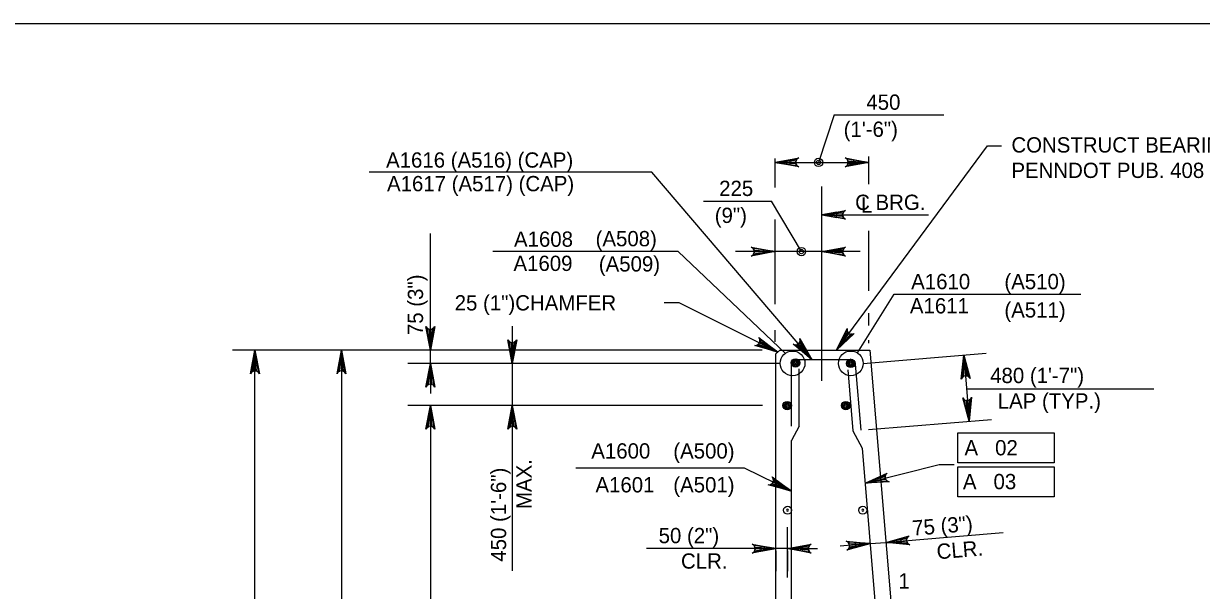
# Model space of a CAD drawing. Extents: x 634540 to 640306, y 296059 to 300275.
# Drawn here: x 638955.4 to 639186.9, y 297715.1 to 297826.5 of the extents above; entities that cross this region are included whole.
import ezdxf

# ---------------------------------------------------------------- set-up
doc = ezdxf.new("R2010")
doc.units = 0
for name, color, linetype in [('2', 7, 'Continuous'), ('3', 7, 'Continuous'), ('4', 7, 'Continuous'), ('5', 7, 'Continuous'), ('9', 7, 'Continuous')]:
    doc.layers.add(name, color=color, linetype=linetype)

# ---------------------------------------------------------------- blocks, each defined once
blk = doc.blocks.new('B')
at = {"layer": '3'}
blk.add_circle((0, 0), 0.16, dxfattribs=at)
for start, end in [(0, 180), (180, 0)]:
    blk.add_arc((0, 0), 0.0391, start, end, dxfattribs=at)

msp = doc.modelspace()

# ---------------------------------------------------------------- linework, layer by layer
at = {"layer": '2'}
msp.add_line((638475.46, 297826.46), (639261.46, 297826.46), dxfattribs=at)
at = {"layer": '3'}
for p, q in [((639114.72, 297808.54), (639111.68, 297799.18)), ((639114.72, 297808.54), (639136.3, 297808.54)), ((639115.23, 297762.31), (639144.88, 297802.43)), ((639144.88, 297802.43), (639147.63, 297802.43)), ((639103.11, 297794.22), (639103.11, 297799.92)), ((639103.11, 297799.18), (639121.57, 297799.18)), ((639121.57, 297794.93), (639121.57, 297800.35)), ((639121.57, 297799.18), (639121.57, 297799.18)), ((639078.88, 297797.23), (639023.32, 297797.23)), ((639110.37, 297760.48), (639078.88, 297797.23)), ((639112.33, 297756.26), (639112.33, 297794.45)), ((639089.02, 297791.54), (639102.44, 297791.54)), ((639108.3, 297781.65), (639102.45, 297791.54)), ((639103.11, 297771.35), (639103.11, 297787.98)), ((639112.33, 297788.88), (639133.31, 297788.88)), ((639035.36, 297759.69), (639035.36, 297785.19)), ((639103.11, 297781.66), (639103.11, 297786.36)), ((639103.11, 297783.06), (639103.11, 297786.08)), ((639121.57, 297773.97), (639121.57, 297785.71)), ((639119.87, 297781.65), (639095.37, 297781.65)), ((639084.26, 297771.61), (639081.31, 297771.61)), ((639103.68, 297761.92), (639084.26, 297771.61)), ((639121.57, 297767.16), (639121.57, 297769.58)), ((639035.36, 297762.31), (639035.36, 297768.21)), ((639051.45, 297767), (639051.45, 297718.96)), ((639103.11, 297763.93), (639103.11, 297766.24)), ((639121.57, 297763.69), (639121.57, 297764.27)), ((639030.22, 297762.31), (638996.44, 297762.31)), ((639000.87, 297600.58), (639000.87, 297762.31)), ((639100.59, 297762.31), (639013.44, 297762.31)), ((639017.87, 297762.31), (639017.87, 297693.66)), ((639017.87, 297762.31), (639017.87, 297762.31)), ((639065.46, 297762.31), (639030.93, 297762.31)), ((639104.04, 297759.69), (639030.93, 297759.69)), ((639035.36, 297759.69), (639035.36, 297753.78)), ((639120.42, 297759.67), (639144.62, 297761.69)), ((639140.2, 297761.32), (639141.29, 297748.32)), ((639140.76, 297754.66), (639177.61, 297754.66)), ((639100.62, 297751.4), (639030.93, 297751.4)), ((639035.36, 297751.4), (639035.36, 297627.86)), ((639121.51, 297746.67), (639145.7, 297748.69)), ((639139.06, 297740.13), (639139.06, 297746.04)), ((639139.06, 297746.04), (639158.01, 297746.04)), ((639158.01, 297746.04), (639158.01, 297740.13)), ((639097.14, 297739.09), (639063.97, 297739.09)), ((639106.36, 297734.57), (639097.14, 297739.09)), ((639120.84, 297736.14), (639135.37, 297739.85)), ((639135.37, 297739.85), (639138.32, 297739.85)), ((639158.01, 297740.13), (639139.06, 297740.13)), ((639139.06, 297739.39), (639158.01, 297739.39)), ((639139.06, 297733.48), (639139.06, 297739.39)), ((639158.01, 297739.39), (639158.01, 297733.48)), ((639158.01, 297733.48), (639139.06, 297733.48)), ((639103.29, 297724.55), (639103.29, 297727.49)), ((639105.58, 297717.61), (639105.58, 297727.49)), ((639124.89, 297724.53), (639130.78, 297725.02)), ((639130.78, 297725.02), (639147.97, 297726.45)), ((639097.38, 297723.3), (639077.86, 297723.3)), ((639100.34, 297723.3), (639097.38, 297723.3)), ((639105.58, 297723.3), (639103.29, 297723.3)), ((639103.29, 297722.86), (639103.29, 297718.87)), ((639105.58, 297722.86), (639105.58, 297718.87)), ((639108.53, 297723.3), (639111.48, 297723.3)), ((639121.83, 297724.28), (639115.94, 297723.79)), ((639121.83, 297724.28), (639124.89, 297724.53))]:
    msp.add_line(p, q, dxfattribs=at)
for points in [[(639103.11, 297799.18), (639107.77, 297800.05), (639107.41, 297799.81), (639107.22, 297799.49), (639107.17, 297799.18), (639107.22, 297798.87), (639107.41, 297798.56), (639107.77, 297798.31), (639103.11, 297799.18), (639107.41, 297798.56), (639107.22, 297798.87), (639103.11, 297799.18), (639107.17, 297799.18), (639107.22, 297799.49), (639103.11, 297799.18), (639107.41, 297799.81)], [(639121.57, 297799.18), (639116.91, 297798.31), (639117.27, 297798.56), (639117.45, 297798.87), (639117.51, 297799.18), (639117.45, 297799.49), (639117.27, 297799.81), (639116.91, 297800.05), (639121.57, 297799.18), (639117.27, 297799.81), (639117.45, 297799.49), (639121.57, 297799.18), (639117.51, 297799.18), (639117.45, 297798.87), (639121.57, 297799.18), (639117.27, 297798.56)], [(639112.33, 297788.88), (639117, 297789.75), (639116.64, 297789.5), (639116.45, 297789.19), (639116.4, 297788.88), (639116.45, 297788.57), (639116.64, 297788.25), (639117, 297788.01), (639112.33, 297788.88), (639116.64, 297788.25), (639116.45, 297788.57), (639112.33, 297788.88), (639116.4, 297788.88), (639116.45, 297789.19), (639112.33, 297788.88), (639116.64, 297789.5)], [(639103.11, 297781.65), (639098.44, 297780.78), (639098.8, 297781.02), (639098.99, 297781.34), (639099.04, 297781.65), (639098.99, 297781.96), (639098.8, 297782.27), (639098.44, 297782.52), (639103.11, 297781.65), (639098.8, 297782.27), (639098.99, 297781.96), (639103.11, 297781.65), (639099.04, 297781.65), (639098.99, 297781.34), (639103.11, 297781.65), (639098.8, 297781.02)], [(639112.33, 297781.65), (639117, 297782.52), (639116.64, 297782.27), (639116.45, 297781.96), (639116.4, 297781.65), (639116.45, 297781.34), (639116.64, 297781.02), (639117, 297780.78), (639112.33, 297781.65), (639116.64, 297781.02), (639116.45, 297781.34), (639112.33, 297781.65), (639116.4, 297781.65), (639116.45, 297781.96), (639112.33, 297781.65), (639116.64, 297782.27)], [(639035.36, 297762.31), (639034.49, 297766.97), (639034.74, 297766.61), (639035.05, 297766.42), (639035.36, 297766.37), (639035.67, 297766.42), (639035.99, 297766.61), (639036.23, 297766.97), (639035.36, 297762.31), (639035.99, 297766.61), (639035.67, 297766.42), (639035.36, 297762.31), (639035.36, 297766.37), (639035.05, 297766.42), (639035.36, 297762.31), (639034.74, 297766.61)], [(639115.23, 297762.31), (639117.3, 297766.57), (639117.29, 297766.14), (639117.43, 297765.8), (639117.65, 297765.57), (639117.93, 297765.43), (639118.29, 297765.4), (639118.7, 297765.54), (639115.23, 297762.31), (639118.29, 297765.4), (639117.93, 297765.43), (639115.23, 297762.31), (639117.65, 297765.57), (639117.43, 297765.8), (639115.23, 297762.31), (639117.29, 297766.14)], [(639051.45, 297759.69), (639050.58, 297764.35), (639050.83, 297763.99), (639051.14, 297763.81), (639051.45, 297763.75), (639051.77, 297763.81), (639052.08, 297763.99), (639052.33, 297764.35), (639051.45, 297759.69), (639052.08, 297763.99), (639051.77, 297763.81), (639051.45, 297759.69), (639051.45, 297763.75), (639051.14, 297763.81), (639051.45, 297759.69), (639050.83, 297763.99)], [(639103.68, 297761.92), (639099.12, 297763.22), (639099.55, 297763.29), (639099.85, 297763.48), (639100.04, 297763.74), (639100.13, 297764.04), (639100.11, 297764.41), (639099.9, 297764.79), (639103.68, 297761.92), (639100.11, 297764.41), (639100.13, 297764.04), (639103.68, 297761.92), (639100.04, 297763.74), (639099.85, 297763.48), (639103.68, 297761.92), (639099.55, 297763.29)], [(639110.37, 297760.48), (639106.67, 297763.45), (639107.09, 297763.34), (639107.45, 297763.4), (639107.72, 297763.57), (639107.92, 297763.81), (639108.04, 297764.15), (639108, 297764.59), (639110.37, 297760.48), (639108.04, 297764.15), (639107.92, 297763.81), (639110.37, 297760.48), (639107.72, 297763.57), (639107.45, 297763.4), (639110.37, 297760.48), (639107.09, 297763.34)], [(639000.87, 297762.31), (639001.74, 297757.65), (639001.49, 297758), (639001.18, 297758.19), (639000.87, 297758.24), (639000.56, 297758.19), (639000.24, 297758), (639000, 297757.65), (639000.87, 297762.31), (639000.24, 297758), (639000.56, 297758.19), (639000.87, 297762.31), (639000.87, 297758.24), (639001.18, 297758.19), (639000.87, 297762.31), (639001.49, 297758)], [(639017.87, 297762.31), (639018.75, 297757.65), (639018.5, 297758), (639018.19, 297758.19), (639017.87, 297758.24), (639017.56, 297758.19), (639017.25, 297758), (639017, 297757.65), (639017.87, 297762.31), (639017.25, 297758), (639017.56, 297758.19), (639017.87, 297762.31), (639017.87, 297758.24), (639018.19, 297758.19), (639017.87, 297762.31), (639018.5, 297758)], [(639035.36, 297759.69), (639036.23, 297755.03), (639035.99, 297755.39), (639035.67, 297755.57), (639035.36, 297755.63), (639035.05, 297755.57), (639034.74, 297755.39), (639034.49, 297755.03), (639035.36, 297759.69), (639034.74, 297755.39), (639035.05, 297755.57), (639035.36, 297759.69), (639035.36, 297755.63), (639035.67, 297755.57), (639035.36, 297759.69), (639035.99, 297755.39)], [(639140.2, 297761.32), (639141.46, 297756.75), (639141.18, 297757.08), (639140.86, 297757.24), (639140.54, 297757.27), (639140.23, 297757.19), (639139.94, 297756.98), (639139.72, 297756.6), (639140.2, 297761.32), (639139.94, 297756.98), (639140.23, 297757.19), (639140.2, 297761.32), (639140.54, 297757.27), (639140.86, 297757.24), (639140.2, 297761.32), (639141.18, 297757.08)], [(639141.29, 297748.32), (639140.03, 297752.89), (639140.31, 297752.55), (639140.63, 297752.4), (639140.95, 297752.37), (639141.26, 297752.45), (639141.55, 297752.66), (639141.77, 297753.04), (639141.29, 297748.32), (639141.55, 297752.66), (639141.26, 297752.45), (639141.29, 297748.32), (639140.95, 297752.37), (639140.63, 297752.4), (639141.29, 297748.32), (639140.31, 297752.55)], [(639035.36, 297751.4), (639036.23, 297746.74), (639035.99, 297747.09), (639035.67, 297747.28), (639035.36, 297747.33), (639035.05, 297747.28), (639034.74, 297747.09), (639034.49, 297746.74), (639035.36, 297751.4), (639034.74, 297747.09), (639035.05, 297747.28), (639035.36, 297751.4), (639035.36, 297747.33), (639035.67, 297747.28), (639035.36, 297751.4), (639035.99, 297747.09)], [(639051.45, 297751.4), (639052.33, 297746.74), (639052.08, 297747.09), (639051.77, 297747.28), (639051.45, 297747.33), (639051.14, 297747.28), (639050.83, 297747.09), (639050.58, 297746.74), (639051.45, 297751.4), (639050.83, 297747.09), (639051.14, 297747.28), (639051.45, 297751.4), (639051.45, 297747.33), (639051.77, 297747.28), (639051.45, 297751.4), (639052.08, 297747.09)], [(639106.36, 297734.57), (639101.79, 297735.84), (639102.22, 297735.9), (639102.52, 297736.1), (639102.71, 297736.36), (639102.8, 297736.66), (639102.77, 297737.02), (639102.56, 297737.4), (639106.36, 297734.57), (639102.77, 297737.02), (639102.8, 297736.66), (639106.36, 297734.57), (639102.71, 297736.36), (639102.52, 297736.1), (639106.36, 297734.57), (639102.22, 297735.9)], [(639120.84, 297736.14), (639125.14, 297738.14), (639124.85, 297737.81), (639124.75, 297737.46), (639124.78, 297737.14), (639124.9, 297736.85), (639125.16, 297736.6), (639125.57, 297736.44), (639120.84, 297736.14), (639125.16, 297736.6), (639124.9, 297736.85), (639120.84, 297736.14), (639124.78, 297737.14), (639124.75, 297737.46), (639120.84, 297736.14), (639124.85, 297737.81)], [(639124.89, 297724.53), (639129.46, 297725.79), (639129.13, 297725.51), (639128.97, 297725.19), (639128.94, 297724.87), (639129.02, 297724.56), (639129.23, 297724.27), (639129.61, 297724.05), (639124.89, 297724.53), (639129.23, 297724.27), (639129.02, 297724.56), (639124.89, 297724.53), (639128.94, 297724.87), (639128.97, 297725.19), (639124.89, 297724.53), (639129.13, 297725.51)], [(639103.29, 297723.3), (639098.63, 297722.42), (639098.99, 297722.67), (639099.17, 297722.98), (639099.23, 297723.3), (639099.17, 297723.61), (639098.99, 297723.92), (639098.63, 297724.17), (639103.29, 297723.3), (639098.99, 297723.92), (639099.17, 297723.61), (639103.29, 297723.3), (639099.23, 297723.3), (639099.17, 297722.98), (639103.29, 297723.3), (639098.99, 297722.67)], [(639105.58, 297723.3), (639110.24, 297724.17), (639109.88, 297723.92), (639109.7, 297723.61), (639109.64, 297723.3), (639109.7, 297722.98), (639109.88, 297722.67), (639110.24, 297722.42), (639105.58, 297723.3), (639109.88, 297722.67), (639109.7, 297722.98), (639105.58, 297723.3), (639109.64, 297723.3), (639109.7, 297723.61), (639105.58, 297723.3), (639109.88, 297723.92)], [(639121.83, 297724.28), (639117.26, 297723.02), (639117.6, 297723.3), (639117.75, 297723.62), (639117.78, 297723.94), (639117.7, 297724.25), (639117.49, 297724.54), (639117.11, 297724.76), (639121.83, 297724.28), (639117.49, 297724.54), (639117.7, 297724.25), (639121.83, 297724.28), (639117.78, 297723.94), (639117.75, 297723.62), (639121.83, 297724.28), (639117.6, 297723.3)]]:
    msp.add_lwpolyline(points, dxfattribs=at)
for points in [[(639106.06, 297798.69), (639106.06, 297799.67), (639103.11, 297799.18)], [(639118.62, 297798.69), (639118.62, 297799.67), (639121.57, 297799.18)], [(639115.29, 297788.38), (639115.29, 297789.37), (639112.33, 297788.88)], [(639034.87, 297765.26), (639035.85, 297765.26), (639035.36, 297762.31)], [(639000.38, 297759.35), (639001.36, 297759.35), (639000.87, 297762.31)], [(639018.37, 297759.35), (639017.38, 297759.35), (639017.87, 297762.31)], [(639101.25, 297763.68), (639100.81, 297762.8), (639103.68, 297761.92)], [(639108.81, 297763.06), (639108.05, 297762.42), (639110.33, 297760.48)], [(639034.87, 297756.74), (639035.85, 297756.74), (639035.36, 297759.69)], [(639140.94, 297758.41), (639139.96, 297758.33), (639140.2, 297761.32)], [(639034.87, 297748.44), (639035.85, 297748.44), (639035.36, 297751.4)], [(639141.53, 297751.31), (639140.55, 297751.22), (639141.29, 297748.32)], [(639124.04, 297736.44), (639123.79, 297737.4), (639121.05, 297736.19)], [(639103.92, 297736.31), (639103.49, 297735.43), (639106.36, 297734.57)], [(639127.8, 297725.27), (639127.88, 297724.29), (639124.89, 297724.53)], [(639100.34, 297723.79), (639100.34, 297722.8), (639103.29, 297723.3)], [(639108.53, 297723.79), (639108.53, 297722.8), (639105.58, 297723.3)], [(639118.85, 297724.52), (639118.93, 297723.54), (639121.83, 297724.28)]]:
    msp.add_lwpolyline(points, close=True, dxfattribs=at)
for centre, radius in [((639111.68, 297799.18), 0.833), ((639111.68, 297799.18), 0.417), ((639108.3, 297781.65), 0.833), ((639108.3, 297781.65), 0.417)]:
    msp.add_circle(centre, radius, dxfattribs=at)
at = {"layer": '4'}
for p, q in [((639084.05, 297781.65), (639047.6, 297781.65)), ((639105.14, 297761.66), (639084.05, 297781.65)), ((639119.3, 297761.75), (639126.56, 297773.26)), ((639126.56, 297773.26), (639163.25, 297773.26))]:
    msp.add_line(p, q, dxfattribs=at)
for centre in [(639106.56, 297759.69), (639118.01, 297759.69)]:
    msp.add_circle(centre, 2.43, dxfattribs=at)
at = {"layer": '5'}
for p, q in [((639107.38, 297760.48), (639117.87, 297760.48)), ((639118.89, 297759.54), (639119.97, 297746.54)), ((639106.36, 297747.38), (639106.36, 297759.46)), ((639107.89, 297747.38), (639107.89, 297758.63)), ((639117.44, 297758.45), (639118.44, 297746.42)), ((639107.89, 297747.38), (639106.36, 297744.54)), ((639118.44, 297746.42), (639120.26, 297743.05)), ((639106.36, 297670.57), (639106.36, 297744.54)), ((639120.26, 297743.05), (639123.87, 297699.77))]:
    msp.add_line(p, q, dxfattribs=at)
for centre, radius in [((639107.13, 297759.78), 0.833), ((639107.13, 297759.78), 0.625), ((639107.13, 297759.78), 0.417), ((639107.13, 297759.78), 0.208), ((639118.01, 297759.69), 0.833), ((639118.01, 297759.69), 0.625), ((639118.01, 297759.69), 0.417), ((639118.01, 297759.69), 0.208), ((639105.5, 297751.4), 0.833), ((639105.5, 297751.4), 0.625), ((639105.5, 297751.4), 0.417), ((639105.5, 297751.4), 0.208), ((639117.02, 297751.4), 0.833), ((639117.02, 297751.4), 0.625), ((639117.02, 297751.4), 0.417), ((639117.02, 297751.4), 0.208)]:
    msp.add_circle(centre, radius, dxfattribs=at)
for centre, start, end in [((639107.38, 297759.46), 90, 180), ((639117.87, 297759.46), 4.7636, 90)]:
    msp.add_arc(centre, 1.03, start, end, dxfattribs=at)
at = {"layer": '9'}
for p, q in [((639103.29, 297761.54), (639104.06, 297762.31)), ((639104.06, 297762.31), (639121.75, 297762.31)), ((639121.75, 297762.31), (639133.16, 297625.29)), ((639103.29, 297663.74), (639103.29, 297761.54))]:
    msp.add_line(p, q, dxfattribs=at)

# ---------------------------------------------------------------- block references
at = {"layer": '3', "xscale": 4.921475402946, "yscale": 4.921475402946, "rotation": 90}
for p in [(639105.58, 297730.84), (639120.37, 297730.84)]:
    msp.add_blockref('B', p, dxfattribs=at)

# ---------------------------------------------------------------- texts
at = {"layer": '3'}
for s, height, p in [('450', 3, (639121.07, 297809.52)), ('(1\'-6")', 3, (639116.61, 297804.2)), ('CONSTRUCT BEARING AREAS AS PER', 3.0001, (639149.59, 297801.12)), ('A1616 (A516) (CAP)', 3.0001, (639026.64, 297798.15)), ('PENNDOT PUB. 408 1001.3(k)8.', 3.0001, (639149.59, 297796.12)), ('A1617 (A517) (CAP)', 3.0001, (639026.83, 297793.51)), ('225', 3, (639092.13, 297792.58)), ('C BRG.', 3, (639118.86, 297789.84)), ('L', 3, (639120.02, 297789.29)), ('(9")', 3, (639091.26, 297787.28)), ('A1608', 3, (639051.79, 297782.6)), ('(A508)', 3, (639067.84, 297782.7)), ('A1609', 3, (639051.69, 297777.85)), ('(A509)', 3, (639068.47, 297777.74)), ('A1610', 3, (639129.88, 297774.27)), ('(A510)', 3, (639148.21, 297774.27)), ('25 (1")CHAMFER', 3.0001, (639040.13, 297770.09)), ('A1611', 3, (639129.63, 297769.51)), ('(A511)', 3, (639148.21, 297768.7)), ('480 (1\'-7")', 3.0001, (639145.41, 297755.82)), ('LAP (TYP.)', 3, (639146.9, 297750.82)), ('A1600', 3, (639066.99, 297740.99)), ('(A500)', 3, (639083.11, 297740.99)), ('A   02', 3, (639140.36, 297741.62)), ('A1601', 3, (639067.81, 297734.34)), ('(A501)', 3, (639083.11, 297734.34)), ('A   03', 3, (639140.05, 297734.97)), ('50 (2")', 3, (639080.23, 297724.36)), ('CLR.', 3, (639084.63, 297719.36)), ('1', 3, (639127.38, 297715.46))]:
    msp.add_text(s, height=height, dxfattribs=at).set_placement(p)
for s, height, rotation, p in [('75 (3")', 3, 90, (639033.91, 297765.25)), ('450 (1\'-6")', 3.0001, 90, (639050.24, 297720.73)), ('MAX.', 3, 90, (639055.24, 297731.08)), ('75 (3")', 3, 4.7636, (639130.22, 297725.81)), ('CLR.', 3, 4.7636, (639135.01, 297721.19))]:
    msp.add_text(s, height=height, rotation=rotation, dxfattribs=at).set_placement(p)

doc.saveas('drawing.dxf')
